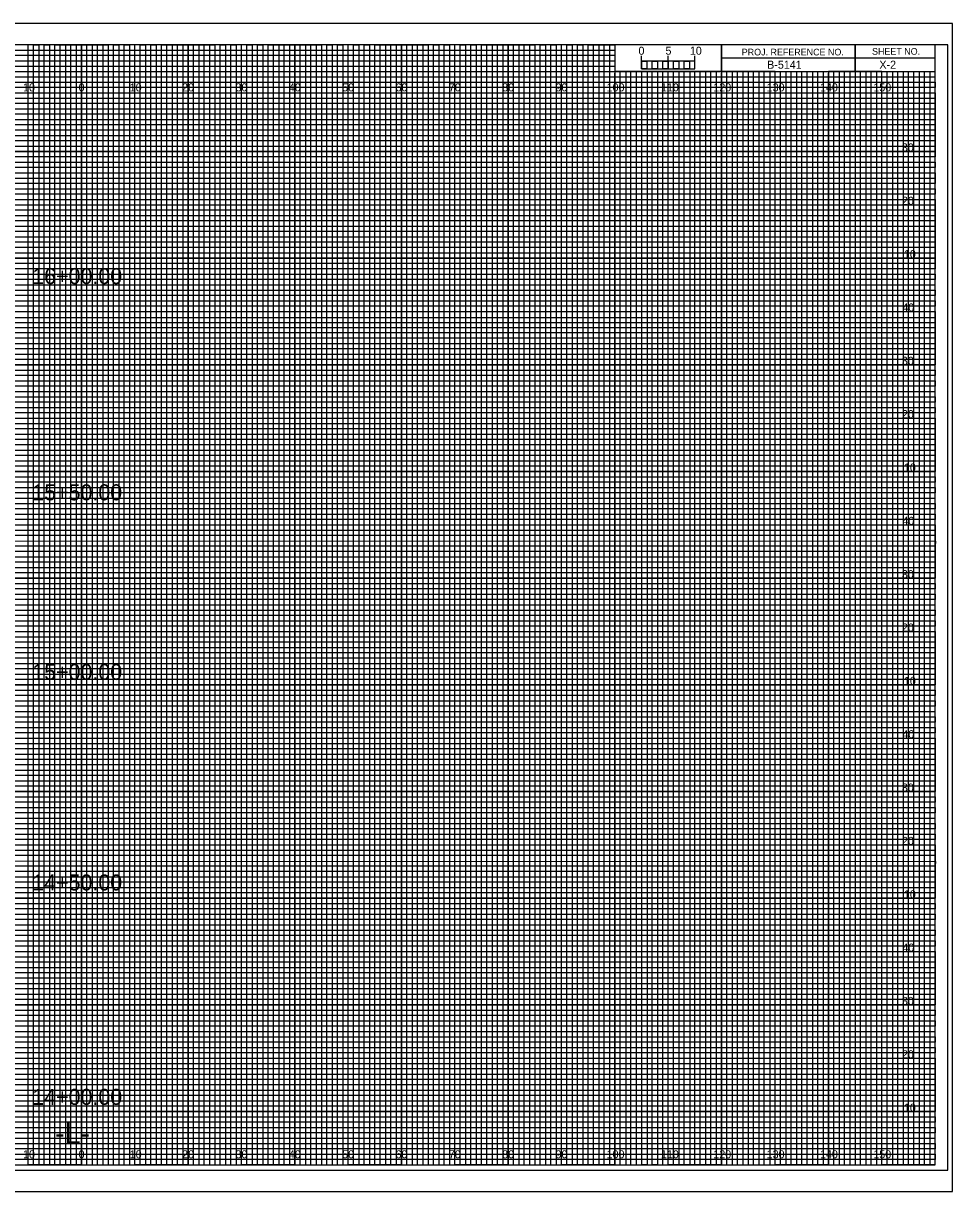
# Model space of a CAD drawing. Extents: x -13 to 323, y 215 to 434.
# Drawn here: x 149.1 to 323.3, y 215 to 434 of the extents above; entities that cross this region are included whole.
import ezdxf

# ---------------------------------------------------------------- set-up
doc = ezdxf.new("R2010")
doc.units = 0
for name, color, linetype in [('Exist Cross Section Cell', 7, 'Continuous'), ('Exist XS Center Line Elevation Label', 7, 'Continuous'), ('Exist XS Ground Line', 7, 'Continuous'), ('Prop XS Alignment Label', 7, 'Continuous'), ('Prop XS Ditch Standard Text', 7, 'Continuous'), ('Prop XS Earthwork Shape', 7, 'Continuous'), ('Prop XS EOT Tick Mark', 7, 'Continuous'), ('Prop XS Finish Grade', 7, 'Continuous'), ('Prop XS Finish Grade Earthwork', 7, 'Continuous'), ('Prop XS Finish Grade Paved Shoulder', 7, 'Continuous'), ('Prop XS Finish Grade Pavement', 7, 'Continuous'), ('Prop XS Pvmt Edge Slope', 7, 'Continuous'), ('Prop XS SE Text', 7, 'Continuous'), ('Prop XS Side Slope Text', 7, 'Continuous'), ('Prop XS Station Labels', 7, 'Continuous'), ('Prop XS Subgrade Earthwork', 7, 'Continuous'), ('Prop XS Undercut Exc', 7, 'Continuous')]:
    doc.layers.add(name, color=color, linetype=linetype)

msp = doc.modelspace()

# ---------------------------------------------------------------- linework, layer by layer
at = {"layer": 'Exist XS Center Line Elevation Label'}
for points in [[(145, 220), (155, 220), (155, 430), (165, 430), (165, 220), (175, 220), (175, 430), (185, 430), (185, 220), (195, 220), (195, 430), (205, 430), (205, 220), (215, 220), (215, 430), (225, 430), (225, 220), (235, 220), (235, 430), (245, 430), (245, 220), (255, 220), (255, 430), (259.93, 430), (260, 430), (260, 425), (264.99, 425), (264.99, 220), (275, 220), (275, 425), (285, 425), (285, 220), (295, 220), (295, 425), (305, 425), (305, 220), (315, 220), (315, 425)], [(0, 425), (275, 425)], [(0, 405), (320, 405), (320, 415), (0, 415)], [(0, 385), (320, 385), (320, 395), (0, 395)], [(0, 365), (320, 365), (320, 375), (0, 375)], [(0, 345), (320, 345), (320, 355), (0, 355)], [(0, 325), (320, 325), (320, 335), (0, 335)], [(0, 305), (320, 305), (320, 315), (0, 315)], [(0, 285), (320, 285), (320, 295), (0, 295)], [(0, 265), (320, 265), (320, 275), (0, 275)], [(0, 245), (320, 245), (320, 255), (0, 255)], [(0, 225), (320, 225), (320, 235), (0, 235)]]:
    msp.add_lwpolyline(points, dxfattribs=at)
at = {"layer": 'Exist XS Ground Line'}
for p, q in [((150, 430), (140, 430)), ((150, 220), (150, 430)), ((170, 430), (160, 430)), ((160, 430), (160, 220)), ((170, 220), (170, 430)), ((190, 430), (180, 430)), ((180, 430), (180, 220)), ((190, 220), (190, 430)), ((210, 430), (200, 430)), ((200, 430), (200, 220)), ((210, 220), (210, 430)), ((230, 430), (220, 430)), ((220, 430), (220, 220)), ((230, 220), (230, 430)), ((250, 430), (240, 430)), ((240, 430), (240, 220)), ((250, 220), (250, 430)), ((260, 430), (260, 220)), ((270, 220), (270, 425)), ((290, 425), (280, 425)), ((280, 425), (280, 220)), ((290, 220), (290, 425)), ((310, 425), (300, 425)), ((300, 425), (300, 220)), ((310, 220), (310, 425)), ((160, 220), (150, 220)), ((180, 220), (170, 220)), ((200, 220), (190, 220)), ((220, 220), (210, 220)), ((240, 220), (230, 220)), ((260, 220), (250, 220)), ((280, 220), (270, 220)), ((300, 220), (290, 220)), ((320, 220), (310, 220)), ((320, 220), (320, 220))]:
    msp.add_line(p, q, dxfattribs=at)
for points in [[(0, 420), (320, 420), (320, 410), (0, 410)], [(0, 400), (320, 400), (320, 390), (0, 390)], [(0, 380), (320, 380), (320, 370), (0, 370)], [(0, 360), (320, 360), (320, 350), (0, 350)], [(0, 340), (320, 340), (320, 330), (0, 330)], [(0, 320), (320, 320), (320, 310), (0, 310)], [(0, 300), (320, 300), (320, 290), (0, 290)], [(0, 280), (320, 280), (320, 270), (0, 270)], [(0, 260), (320, 260), (320, 250), (0, 250)], [(0, 240), (320, 240), (320, 230), (0, 230)]]:
    msp.add_lwpolyline(points, dxfattribs=at)
at = {"layer": 'Prop XS Alignment Label'}
for p, q in [((0, 429), (260, 429)), ((260, 427.98), (0, 427.98)), ((260, 429), (260, 427.98)), ((0, 427), (260, 427)), ((260, 425.89), (0, 425.89)), ((260, 427), (260, 425.89)), ((0, 424), (320, 424))]:
    msp.add_line(p, q, dxfattribs=at)
for points in [[(0, 423), (270, 423), (320, 423), (320, 422), (0, 422)], [(0, 421), (320, 421), (320, 419), (0, 419)], [(0, 418), (320, 418), (320, 417), (0, 416.98)], [(0, 416), (320, 416), (320, 414), (0, 414)], [(0, 413), (320, 413), (320, 412), (0, 412)], [(0, 411), (320, 411), (320, 409), (0, 409)], [(0, 408), (320, 408), (320, 407), (0, 407)], [(0, 406), (320, 406), (320, 404), (0, 404)], [(0, 403), (320, 403), (320, 402), (0, 402)], [(0, 401), (320, 401), (320, 399), (0, 399)], [(0, 398), (320, 398), (320, 397), (0, 397)], [(0, 396), (320, 396), (320, 393.95), (320, 393), (320, 392), (0, 392)], [(0, 394), (320, 394), (320, 393), (0, 393)], [(0, 391), (320, 391), (320, 389), (0, 389.03)], [(0, 389.03), (320, 389), (320, 388), (0, 388)], [(0, 387), (320, 387), (320, 386), (0, 386)], [(0, 384), (320, 384), (320, 383), (0, 383)], [(0, 382), (320, 382), (320, 381), (0, 381)], [(-0.07, 378.89), (320, 378.89), (320, 377.88), (-0.07, 377.88)], [(0, 377), (320, 377), (320, 376), (0, 376)], [(0, 374), (320, 374), (320, 373), (0, 373)], [(0, 372), (320, 372), (320, 371), (0, 371)], [(0, 369), (320, 369), (320, 368), (0, 368)], [(0, 367), (320, 367), (320, 366), (0, 366)], [(0, 364), (320, 364), (320, 363), (0, 363)], [(0, 362), (320, 362), (320, 361), (0, 361)], [(0, 359), (320, 359), (319.99, 357.98), (0, 358)], [(0, 357), (320, 357), (320, 356), (0, 356)], [(0, 354), (320, 354), (320, 353), (0, 353)], [(0, 352), (320, 352), (320, 351), (0, 351)], [(0, 349), (320, 349), (320, 348), (0, 348)], [(0, 347), (320, 347), (320, 346), (0, 346)], [(0, 344), (320, 344), (320, 343), (0, 343)], [(0, 342), (320, 342), (320, 341), (0, 341)], [(0, 339), (320, 339), (320, 338), (0, 338)], [(0, 336.99), (320.07, 336.91), (320, 336), (0, 336)], [(0, 334), (320, 334), (320, 333), (0, 333)], [(0, 332), (320, 332), (320, 331), (0, 331)], [(0, 329), (320, 329), (320, 328), (0, 328)], [(0, 327), (320, 327), (320, 326), (0, 326)], [(0, 324), (320, 324), (320, 323), (0, 323)], [(0, 322), (320, 322), (320, 321), (0, 321)], [(0, 319), (320, 319), (320, 318), (0, 318)], [(0, 317), (320, 317), (320, 316), (0, 316)], [(0, 314), (320, 314), (320, 313), (0, 313)], [(0, 312), (320, 312), (320, 311), (0, 311)], [(0, 309), (320, 309), (320, 308), (0, 308)], [(0, 307), (320, 307), (320, 306), (0, 306)], [(0, 304), (320, 304), (320, 303), (0, 303)], [(0, 302), (320, 302), (320, 301), (0, 301)], [(0, 299), (320, 299), (319.99, 297.98), (0, 298)], [(0, 297), (320, 297), (320, 296), (0, 296)], [(0, 294), (320, 294), (320, 293), (0, 293)], [(0, 292), (320, 292), (320, 291), (0, 291)], [(0, 289), (320, 289), (320, 288), (0, 288)], [(0, 287), (320, 287), (320, 286), (0, 286)], [(0, 284), (320, 284), (320, 283), (0, 283)], [(0, 282), (320, 282), (320, 281), (0, 281)], [(0, 279), (320, 279), (320, 278), (0, 278)], [(0, 276.99), (320.07, 276.91), (320, 276), (0, 276)], [(0, 274), (320, 274), (320, 273), (0, 273)], [(0, 272), (320, 272), (320, 271), (0, 271)], [(0, 269), (320, 269), (320, 268), (0, 268)], [(0, 267), (320, 267), (320, 266), (0, 266)], [(0, 264), (320, 264), (320, 263), (0, 263)], [(0, 262), (320, 262), (320, 261), (0, 261)], [(0, 259), (320, 259), (320, 258), (0, 258)], [(0, 257), (320, 257), (320, 256), (0, 256)], [(0, 254), (320, 254), (320, 253), (0, 253)], [(0, 252), (320, 252), (320, 251), (0, 251)], [(0, 249), (320, 249), (320, 248), (0, 248)], [(0, 247), (320, 247), (320, 246), (0, 246)], [(0, 244), (320, 244), (320, 243), (0, 243)], [(0, 242), (320, 242), (320, 241), (0, 241)], [(0, 239), (320, 239), (320, 238), (0, 238)], [(0, 237), (320, 237), (320, 236), (0, 236)], [(0, 234), (320, 234), (320, 233), (0, 233)], [(0, 232), (320, 232), (320, 231), (0, 231)], [(0, 229), (320, 229), (320, 228), (0, 228)], [(0, 227), (320, 227), (320, 226), (0, 226)], [(0, 224), (320, 224), (320, 223), (0, 223)], [(0, 222), (320, 222), (320, 221), (0, 221)]]:
    msp.add_lwpolyline(points, dxfattribs=at)
at = {"layer": 'Prop XS Ditch Standard Text'}
for p, q in [((150, 220), (150, 430)), ((160, 220), (160, 430)), ((170, 220), (170, 430)), ((180, 220), (180, 430)), ((190, 220), (190, 430)), ((200, 220), (200, 430)), ((210, 220), (210, 430)), ((220, 220), (220, 430)), ((230, 220), (230, 430)), ((240, 220), (240, 430)), ((250, 220), (250, 430)), ((260, 220), (260, 424.69)), ((270, 220), (270, 424.69)), ((280, 220), (280, 424.69)), ((290, 220), (290, 424.69)), ((300, 220), (300, 424.69)), ((310, 220), (310, 424.69)), ((0, 420), (320, 420)), ((0, 410), (320, 410)), ((0, 400), (320, 400)), ((0, 390), (320, 390)), ((0, 380), (320, 380)), ((0, 370), (320, 370)), ((0, 360), (320, 360)), ((0, 350), (320, 350)), ((0, 340), (320, 340)), ((0, 330), (320, 330)), ((0, 320), (320, 320)), ((0, 310), (320, 310)), ((0, 300), (320, 300)), ((0, 290), (320, 290)), ((0, 280), (320, 280)), ((0, 270), (320, 270)), ((0, 260), (320, 260)), ((0, 250), (320, 250)), ((0, 240), (320, 240)), ((0, 230), (320, 230))]:
    msp.add_line(p, q, dxfattribs=at)
at = {"layer": 'Prop XS Earthwork Shape'}
for p, q in [((267, 425), (266.01, 425)), ((266.01, 425), (266.01, 220)), ((267, 220), (267, 425)), ((269, 425), (268, 425)), ((268, 425), (268, 220)), ((269, 220), (269, 425)), ((266.01, 220), (265, 220)), ((268, 220), (267, 220))]:
    msp.add_line(p, q, dxfattribs=at)
for points in [[(150, 220), (151, 220), (151, 430), (152, 430), (152, 220)], [(152, 220), (153, 220), (153, 430), (154, 430), (154, 220)], [(155, 220), (156, 220), (156, 430), (157, 430), (157, 220)], [(157, 220), (158, 220), (158, 430), (159, 430), (159, 220)], [(160, 220), (161, 220), (161, 430), (162, 430), (162, 220)], [(162, 220), (163, 220), (163, 430), (164, 430), (164, 220)], [(165, 220), (166, 220), (166, 430), (167, 430), (167, 220)], [(167, 220), (168, 220), (168, 430), (169, 430), (169, 220)], [(170, 220), (171, 220), (171, 430), (172, 430), (172, 220)], [(172, 220), (173, 220), (173, 430), (174, 430), (174, 220)], [(175, 220), (176, 220), (176, 430), (177, 430), (177, 220)], [(177, 220), (178, 220), (178, 430), (179, 430), (179, 220)], [(180, 220), (181, 220), (181, 430), (182, 430), (182, 220)], [(182, 220), (183, 220), (183, 430), (184, 430), (184, 220)], [(185, 220), (186, 220), (186, 430), (187, 430), (187, 220)], [(187, 220), (188, 220), (188, 430), (189, 430), (189, 220)], [(190, 220), (191, 220), (191, 430), (192, 430), (192, 220)], [(192, 220), (193, 220), (193, 430), (194, 430), (194, 220)], [(195, 220), (196, 220), (196, 430), (197, 430), (197, 220)], [(197, 220), (198, 220), (198, 430), (199, 430), (199, 220)], [(200, 220), (201, 220), (201, 430), (202, 430), (202, 220)], [(202, 220), (203, 220), (203, 430), (204, 430), (204, 220)], [(205, 220), (206, 220), (206, 430), (207, 430), (207, 220)], [(207, 220), (208, 220), (208, 430), (209, 430), (209, 220)], [(210, 220), (211, 220), (211, 430), (212, 430), (212, 220)], [(212, 220), (213, 220), (213, 430), (214, 430), (214, 220)], [(215, 220), (216, 220), (216, 430), (217, 430), (217, 220)], [(217, 220), (218, 220), (218, 430), (219, 430), (219, 220)], [(220, 220), (221, 220), (221, 430), (222, 430), (222, 220)], [(222, 220), (223, 220), (223, 430), (224, 430), (224, 220)], [(225, 220), (226, 220), (226, 430), (227, 430), (227, 220)], [(227, 220), (228, 220), (228, 430), (229, 430), (229, 220)], [(230, 220), (231, 220), (231, 430), (232, 430), (232, 220)], [(232, 220), (233, 220), (233, 430), (234, 430), (234, 220)], [(235, 220), (236, 220), (236, 430), (237, 430), (237, 220)], [(237, 220), (238, 220), (238, 430), (239, 430), (239, 220)], [(240, 220), (241, 220), (241, 430), (242, 430), (242, 220)], [(242, 220), (243, 220), (243, 430), (244, 430), (244, 220)], [(245, 220), (246, 220), (246, 430), (247, 430), (247, 220)], [(247, 220), (248, 220), (248, 430), (249, 430), (249, 220)], [(250, 220), (251, 220), (251, 430), (252, 430), (252, 220)], [(252, 220), (253, 220), (253, 430), (254, 430), (254, 220)], [(255, 220), (256, 220), (256, 430), (257, 430), (257, 220)], [(257, 220), (258, 220), (258, 430), (259, 430), (259, 220)], [(260, 220), (261, 220), (261, 425), (262.02, 425), (262.02, 220)], [(262, 220), (263, 220), (263, 425), (263.99, 425), (263.99, 220)], [(270, 220), (270.98, 220), (270.98, 425), (272, 425), (272, 220)], [(272, 220), (273, 220), (273, 425), (274.05, 425), (274.05, 220)], [(275, 220), (276, 220), (276, 425), (277, 425), (277, 220)], [(277, 220), (278, 220), (278, 425), (279, 425), (279, 220)], [(280, 220), (281, 220), (281, 425), (282, 425), (282, 220)], [(282, 220), (283, 220), (283, 425), (284, 425), (284, 220)], [(285, 220), (286, 220), (286, 425), (287, 425), (287, 220)], [(287, 220), (288, 220), (288, 425), (289, 425), (289, 220)], [(290, 220), (291, 220), (291, 425), (292, 425), (292, 220)], [(292, 220), (293, 220), (293, 425), (294, 425), (294, 220)], [(295, 220), (296, 220), (296, 425), (297, 425), (297, 220)], [(297, 220), (298, 220), (298, 425), (299, 425), (299, 220)], [(300, 220), (301, 220), (301, 425), (302, 425), (302, 220)], [(302, 220), (303, 220), (303, 425), (304, 425), (304, 220)], [(305, 220), (306, 220), (306, 425), (307, 425), (307, 220)], [(307, 220), (308, 220), (308, 425), (309, 425), (309, 220)], [(310, 220), (311, 220), (311, 425), (312, 425), (312, 220)], [(312, 220), (313, 220), (313, 425), (314, 425), (314, 220)], [(315, 220), (316, 220), (316, 425), (317, 425), (317, 220)], [(317, 220), (318, 220), (318, 425), (319, 425), (319, 220)]]:
    msp.add_lwpolyline(points, dxfattribs=at)
at = {"layer": 'Prop XS Finish Grade Earthwork'}
for p, q in [((323.3, 434), (-13.4, 434)), ((-13.4, 215), (323.3, 215))]:
    msp.add_line(p, q, dxfattribs=at)
at = {"layer": 'Prop XS SE Text'}
for p, q in [((305, 430), (305, 425)), ((305, 425), (305, 430)), ((280, 427.5), (280, 425)), ((320, 427.49), (280, 427.49)), ((280, 425), (320, 425))]:
    msp.add_line(p, q, dxfattribs=at)
for points in [[(320, 430), (0, 430), (0, 220), (320, 220)], [(280, 430), (260, 430), (260, 425.03), (280, 425.03)], [(320, 430), (280, 430), (280, 425), (320, 425)]]:
    msp.add_lwpolyline(points, close=True, dxfattribs=at)
at = {"layer": 'Prop XS Side Slope Text'}
for p, q in [((265, 425.49), (265, 427.9)), ((265, 426.9), (265, 427.9)), ((270, 425.49), (270, 427.9)), ((275, 425.49), (275, 427.9)), ((275, 426.9), (275, 427.9))]:
    msp.add_line(p, q, dxfattribs=at)
for points in [[(275, 426.9), (265, 426.9), (265, 425.49), (275, 425.49)], [(265, 426.9), (266, 426.9), (266, 425.49), (265, 425.49)], [(267, 426.9), (268, 426.9), (268, 425.49), (267, 425.49)], [(269, 426.9), (270, 426.9), (270, 425.49), (269, 425.49)], [(271, 426.9), (272, 426.9), (272, 425.49), (271, 425.49)], [(273, 426.9), (274, 426.9), (274, 425.49), (273, 425.49)]]:
    msp.add_lwpolyline(points, close=True, dxfattribs=at)
at = {"layer": 'Prop XS Station Labels'}
msp.add_lwpolyline([(-10.8, 219), (322.4, 219), (322.4, 430), (-10.8, 430)], close=True, dxfattribs=at)
at = {"layer": 'Prop XS Undercut Exc'}
msp.add_lwpolyline([(-13.4, 215), (323.3, 215), (323.3, 434), (-13.4, 434)], close=True, dxfattribs=at)

# ---------------------------------------------------------------- texts
at = {"layer": 'Exist Cross Section Cell'}
for s, p in [('10', (149.04, 421.25)), ('0', (159.45, 421.25)), ('0', (159.45, 421.25)), ('10', (169.04, 421.25)), ('20', (178.86, 421.25)), ('30', (188.86, 421.25)), ('40', (198.86, 421.25)), ('50', (208.86, 421.25)), ('60', (218.86, 421.25)), ('70', (228.86, 421.25)), ('80', (238.86, 421.25)), ('90', (248.86, 421.25)), ('100', (258.44, 421.25)), ('110', (268.62, 421.25)), ('120', (278.44, 421.25)), ('130', (288.44, 421.25)), ('140', (298.44, 421.25)), ('150', (308.44, 421.25)), ('10', (149.04, 221.25)), ('0', (159.45, 221.25)), ('0', (159.45, 221.25)), ('10', (169.04, 221.25)), ('20', (178.86, 221.25)), ('30', (188.86, 221.25)), ('40', (198.86, 221.25)), ('50', (208.86, 221.25)), ('60', (218.86, 221.25)), ('70', (228.86, 221.25)), ('80', (238.86, 221.25)), ('90', (248.86, 221.25)), ('100', (258.44, 221.25)), ('110', (268.62, 221.25)), ('120', (278.44, 221.25)), ('130', (288.44, 221.25)), ('140', (298.44, 221.25)), ('150', (308.44, 221.25))]:
    msp.add_text(s, height=1.5, dxfattribs=at).set_placement(p)
at = {"layer": 'Prop XS EOT Tick Mark'}
msp.add_text('-L-', height=4, dxfattribs=at).set_placement((155.06, 224))
at = {"layer": 'Prop XS Finish Grade'}
for s, p in [('30', (313.78, 410)), ('20', (313.8, 400)), ('10', (314.17, 390)), ('40', (313.87, 380)), ('30', (313.78, 370)), ('20', (313.8, 360)), ('10', (314.17, 350)), ('40', (313.87, 340)), ('30', (313.78, 330)), ('20', (313.8, 320)), ('10', (314.17, 310)), ('40', (313.87, 300)), ('30', (313.78, 290)), ('20', (313.8, 280)), ('10', (314.17, 270)), ('40', (313.87, 260)), ('30', (313.78, 250)), ('20', (313.8, 240)), ('10', (314.17, 230))]:
    msp.add_text(s, height=1.5, dxfattribs=at).set_placement(p)
at = {"layer": 'Prop XS Finish Grade Paved Shoulder'}
msp.add_text('X-2', height=1.5, dxfattribs=at).set_placement((309.57, 425.5))
at = {"layer": 'Prop XS Finish Grade Pavement'}
for s, p in [('5', (269.47, 428.12)), ('10', (274.04, 428.12))]:
    msp.add_text(s, height=1.5, dxfattribs=at).set_placement(p)
at = {"layer": 'Prop XS Pvmt Edge Slope'}
msp.add_text('B-5141', height=1.5, dxfattribs=at).set_placement((288.53, 425.5))
at = {"layer": 'Prop XS SE Text'}
for s, p in [('PROJ. REFERENCE NO.', (283.77, 427.99)), ('SHEET NO.', (308.19, 428.12))]:
    msp.add_text(s, height=1.25, dxfattribs=at).set_placement(p)
at = {"layer": 'Prop XS Side Slope Text'}
msp.add_text('0', height=1.5, dxfattribs=at).set_placement((264.41, 428.12))
at = {"layer": 'Prop XS Subgrade Earthwork'}
for s, p in [('16+00.00', (150.77, 385.13)), ('15+50.00', (150.77, 344.59)), ('15+00.00', (150.77, 310.92)), ('14+50.00', (150.77, 271.46)), ('14+00.00', (150.77, 231.27))]:
    msp.add_text(s, height=3, dxfattribs=at).set_placement(p)

doc.saveas('drawing.dxf')
